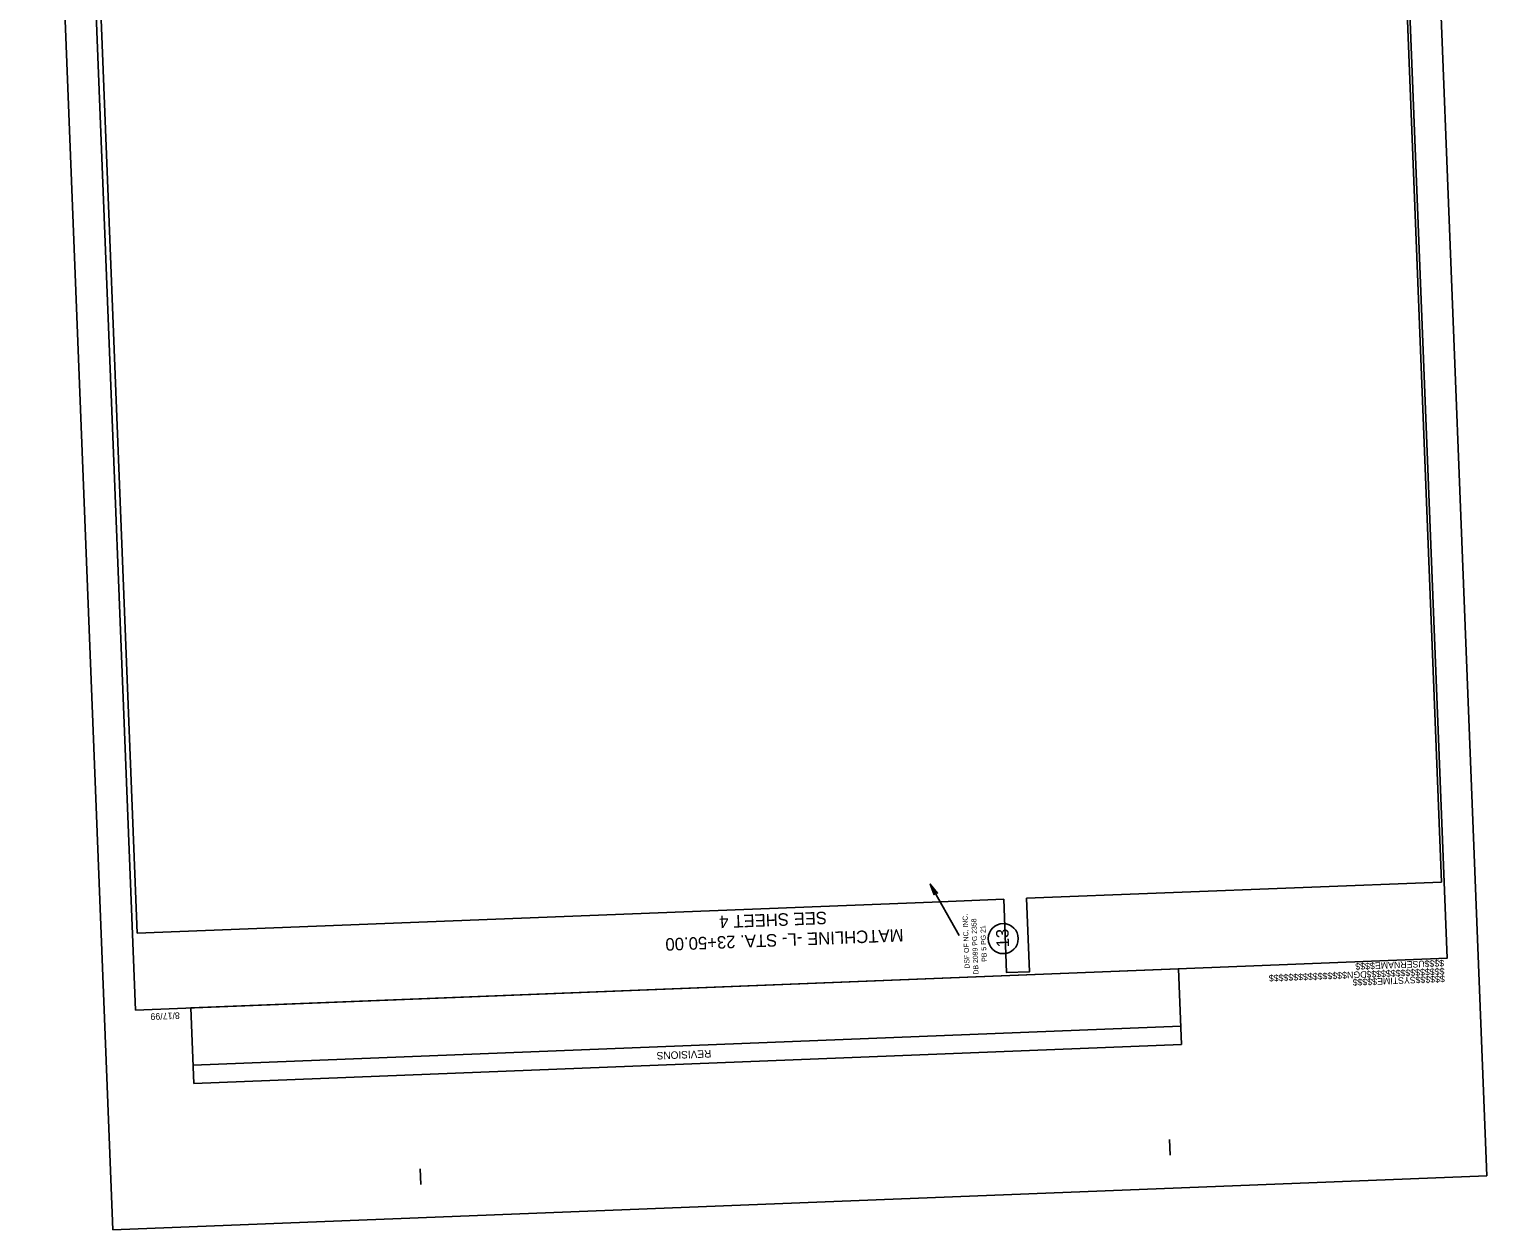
# Model space of a CAD drawing. Extents: x 1627855 to 1629021, y 762567 to 764488.
# Drawn here: x 1627855 to 1629021, y 762567 to 763528 of the extents above; entities that cross this region are included whole.
import ezdxf

# ---------------------------------------------------------------- set-up
doc = ezdxf.new("R2010")
doc.units = 0
for name, color, linetype in [('Matchline', 7, 'Continuous'), ('Matchline Text', 7, 'Continuous'), ('Prop Dimension', 7, 'Continuous'), ('Prop Parcel Number CELL', 7, 'Continuous'), ('Prop Parcel Owner Text', 7, 'Continuous'), ('Prop Terminator CELL', 7, 'Continuous'), ('Sheet Block Revision CELL', 7, 'Continuous'), ('Sheet Block System Information CELL', 7, 'Continuous'), ('Sheet Clip Boundary CELL', 7, 'Continuous'), ('Sheet Plan And Profile CELL', 7, 'Continuous'), ('Sheet Plot Border Outside CELL', 7, 'Continuous')]:
    doc.layers.add(name, color=color, linetype=linetype)

msp = doc.modelspace()

# ---------------------------------------------------------------- linework, layer by layer
at = {"layer": 'Matchline'}
msp.add_line((1628577.6, 762829.6), (1628337.8, 762820.2), dxfattribs=at)
at = {"layer": 'Prop Dimension'}
msp.add_line((1628599.1, 762802.9), (1628576, 762843.9), dxfattribs=at)
at = {"layer": 'Prop Parcel Number CELL'}
msp.add_line((1628634.4, 762800.3), (1628634.4, 762800.3), dxfattribs=at)
msp.add_circle((1628634.4, 762800.3), 12, dxfattribs=at)
at = {"layer": 'Prop Terminator CELL'}
msp.add_lwpolyline([(1628579.1, 762835.3), (1628576, 762843.9), (1628581.9, 762836.8), (1628579.9, 762837)], close=True, dxfattribs=at)
at = {"layer": 'Sheet Block Revision CELL'}
msp.add_line((1628776.4, 762730.2), (1627986.3, 762699), dxfattribs=at)
msp.add_lwpolyline([(1628776.9, 762715.6), (1627986.9, 762684.5), (1627984.5, 762745), (1628774.5, 762776.1)], close=True, dxfattribs=at)
at = {"layer": 'Sheet Block System Information CELL'}
msp.add_line((1628989.4, 762784.6), (1628989.4, 762784.6), dxfattribs=at)
at = {"layer": 'Sheet Clip Boundary CELL'}
msp.add_lwpolyline([(1628522.5, 764228.5), (1628282.7, 764219.1), (1628066.5, 764210.3), (1628072.9, 764047.5), (1627958.4, 764043), (1627966.3, 763843.3), (1627900.7, 763840.7), (1627941.6, 762804.7), (1628337.8, 762820.2), (1628577.6, 762829.6), (1628634.8, 762831.8), (1628637.1, 762773.1), (1628655.4, 762773.8), (1628653.1, 762832.6), (1628984.9, 762845.6), (1628929.7, 764244.5)], close=True, dxfattribs=at)
at = {"layer": 'Sheet Plan And Profile CELL'}
for p, q in [((1628989.4, 762784.6), (1628989.4, 762784.6)), ((1628989.4, 762784.6), (1628989.4, 762784.6)), ((1628989.4, 762784.6), (1628989.4, 762784.6)), ((1628989.4, 762784.6), (1628989.4, 762784.6)), ((1628989.4, 762784.6), (1628989.4, 762784.6)), ((1628767.9, 762627.2), (1628767.4, 762639.7)), ((1628168.4, 762603.6), (1628167.9, 762616.1))]:
    msp.add_line(p, q, dxfattribs=at)
msp.add_lwpolyline([(1627881.1, 764242), (1627940.2, 762743.2), (1628989.4, 762784.6), (1628930.3, 764283.4)], close=True, dxfattribs=at)
at = {"layer": 'Sheet Plot Border Outside CELL'}
msp.add_lwpolyline([(1629021.3, 762610.7), (1628954.3, 764309.4), (1627855.1, 764266), (1627922.1, 762567.4)], close=True, dxfattribs=at)

# ---------------------------------------------------------------- texts
at = {"layer": 'Matchline Text'}
for s, p in [('SEE SHEET 4', (1628493.2, 762822)), ('MATCHLINE -L- STA. 23+50.00', (1628554.4, 762808.1))]:
    msp.add_text(s, height=10, rotation=182.2582, dxfattribs=at).set_placement(p)
at = {"layer": 'Prop Parcel Number CELL'}
msp.add_text('13', height=10, rotation=92.2582, dxfattribs=at).set_placement((1628639.1, 762793.5))
at = {"layer": 'Prop Parcel Owner Text'}
for s, p in [('DSF OF NC, INC.', (1628607.5, 762776.4)), ('DB 2099 PG 2358', (1628614.6, 762771.7)), ('PB 5 PG 21', (1628621.2, 762781.9))]:
    msp.add_text(s, height=4, rotation=92.2582, dxfattribs=at).set_placement(p)
at = {"layer": 'Sheet Block Revision CELL'}
msp.add_text('REVISIONS', height=6, rotation=182.2582, dxfattribs=at).set_placement((1628400.7, 762711.3))
at = {"layer": 'Sheet Block System Information CELL'}
for s, p in [('$$$$USERNAME$$$$', (1628987, 762783.4)), ('$$$$$$$$$$$$$$$$DGN$$$$$$$$$$$$$$$$', (1628987.3, 762776.8)), ('$$$$$$SYSTIME$$$$$', (1628987.6, 762770.8))]:
    msp.add_text(s, height=5.25, rotation=182.2582, dxfattribs=at).set_placement(p)
at = {"layer": 'Sheet Plan And Profile CELL'}
msp.add_text('8/17/99', height=5.25, rotation=182.2582, dxfattribs=at).set_placement((1627975.5, 762741.4))

doc.saveas('drawing.dxf')
